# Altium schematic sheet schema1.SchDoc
size A3; ApprovedBy: CdB; CheckedBy: CdB; DrawnBy: RT; Engineer: CdB; Organization: Faber Electronics B.V.; Address1: Th. Dobbeweg 1,; Address2: 6883 GN Velp,; Address3: Netherlands; Address4: T: 026-38 46 800; DocumentNumber: 1; Revision: 2.1.4; SheetNumber: 1; SheetTotal: 6; Status: Final; PageSetup: Record=PageOptions|CenterHorizontal=True|CenterVertical=True|PrintScale=1.01|XCorrection=1.00|YCorrection=1.00|PrintKind=1|BorderSize=5000000|LeftOffset=0|BottomOffset=0|Orientation=2|PaperLength=1000|PaperWidth=1000|Scale=100|PaperSource=7|PrintQuality=1200|MediaType=1|DitherType=10|PaperKind=A3 (297 x 420mm)|PrintScaleMode=1
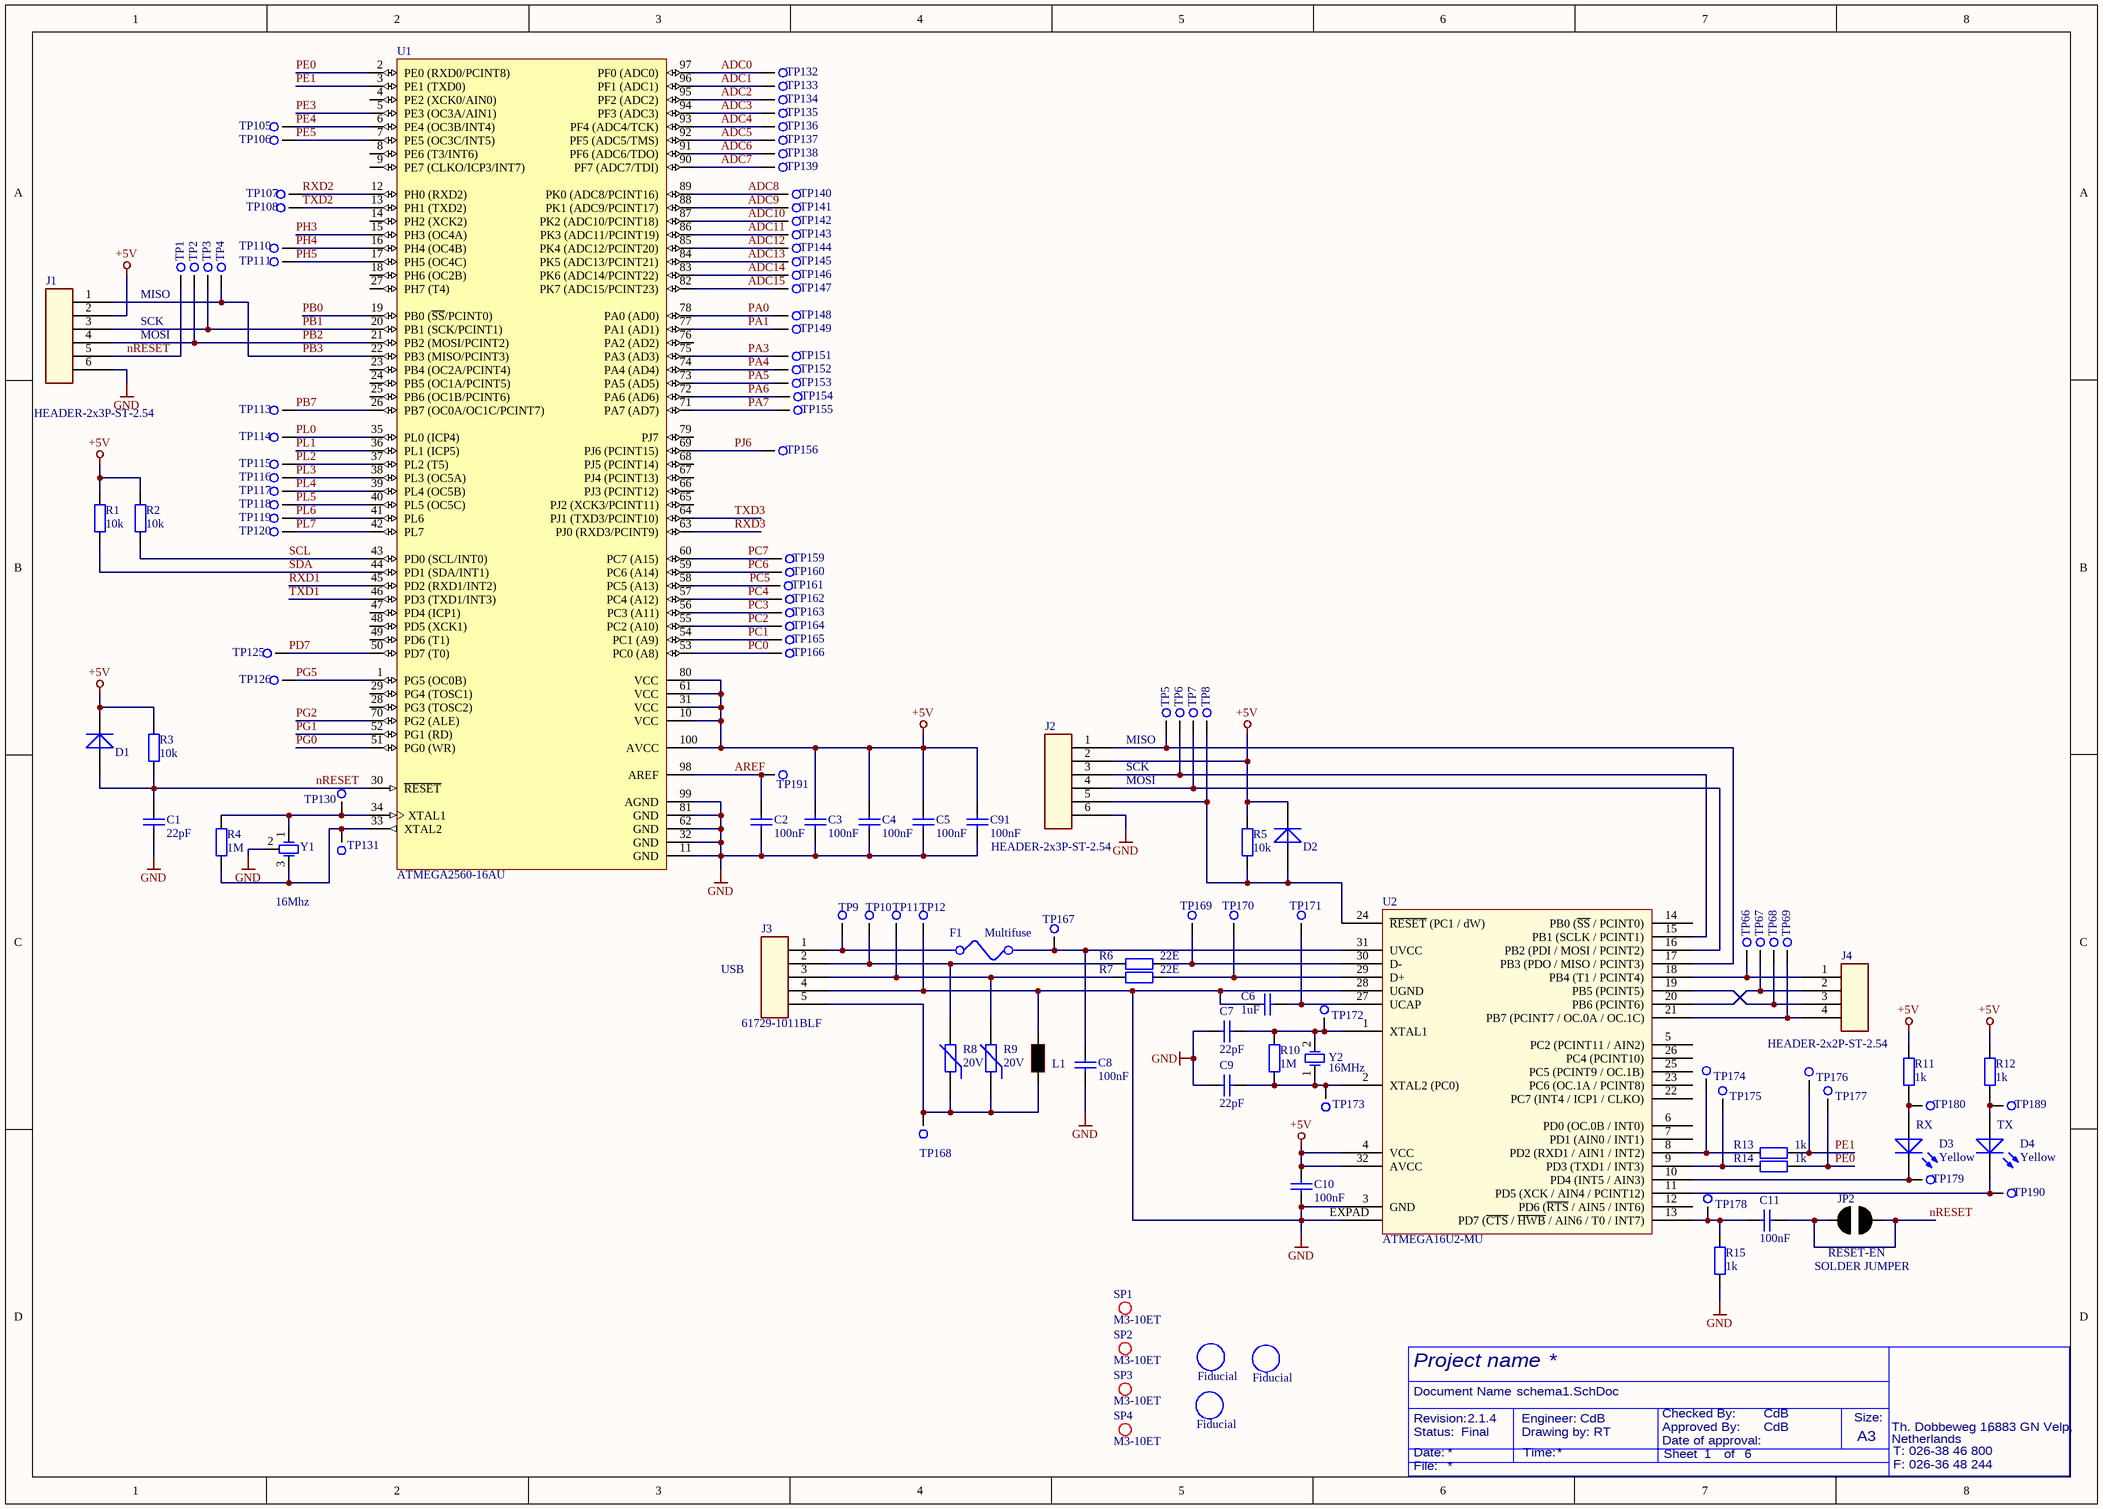
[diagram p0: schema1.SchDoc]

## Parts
C1  22pF  [C0603]
C2  100nF  [C0603]
C3  100nF  [C0603]
C4  100nF  [C0603]
C5  100nF  [C0603]
C6  1uF  [C0603]
C7  22pF  [C0603]
C8  100nF  [C0603]
C9  22pF  [C0603]
C10  100nF  [C0603]
C11  100nF  [C0603]
C91  100nF  [C0603]
D1  1N4148  [SOD323]  (value not drawn)
D2  1N4148  [SOD323]  (value not drawn)
D3  Yellow  [LED0805-YELLOW]
D4  Yellow  [LED0805-YELLOW]
F1  Multifuse  [Multifuse1812]
Fid1  Fiducial  [Fiducial]  (no BOM)
Fid2  Fiducial  [Fiducial]  (no BOM)
Fid3  Fiducial  [Fiducial]  (no BOM)
J1  HEADER-2x3P-ST-2.54  [HEADER-2x3P-ST-2.54]
J2  HEADER-2x3P-ST-2.54  [HEADER-2x3P-ST-2.54]
J3  61729-1011BLF  [61729-1011BLF]
J4  HEADER-2x2P-ST-2.54  [HEADER-2x2P-ST-2.54]
JP2  SOLDER JUMPER  [JUMPER 2 SOLDER]
L1  Bead  [L0805]  (value not drawn)
R1  10k  [R0603]
R2  10k  [R0603]
R3  10k  [R0603]
R4  1M  [R0603]
R5  10k  [R0603]
R6  22E  [R0603]
R7  22E  [R0603]
R8  20V  [R0603]
R9  20V  [R0603]
R10  1M  [R0603]
R11  1k  [R0603]
R12  1k  [R0603]
R13  1k  [R0603]
R14  1k  [R0603]
R15  1k  [R0603]
SP1  M3-10ET  [Spacer M3-10ET]
SP2  M3-10ET  [Spacer M3-10ET]
SP3  M3-10ET  [Spacer M3-10ET]
SP4  M3-10ET  [Spacer M3-10ET]
TP1  Testpoint  [Testpoint]  (value not drawn)
TP2  Testpoint  [Testpoint]  (value not drawn)
TP3  Testpoint  [Testpoint]  (value not drawn)
TP4  Testpoint  [Testpoint]  (value not drawn)
TP5  Testpoint  [Testpoint]  (value not drawn)
TP6  Testpoint  [Testpoint]  (value not drawn)
TP7  Testpoint  [Testpoint]  (value not drawn)
TP8  Testpoint  [Testpoint]  (value not drawn)
TP9  Testpoint  [Testpoint]  (value not drawn)
TP10  Testpoint  [Testpoint]  (value not drawn)
TP11  Testpoint  [Testpoint]  (value not drawn)
TP12  Testpoint  [Testpoint]  (value not drawn)
TP66  Testpoint  [Testpoint]  (value not drawn)
TP67  Testpoint  [Testpoint]  (value not drawn)
TP68  Testpoint  [Testpoint]  (value not drawn)
TP69  Testpoint  [Testpoint]  (value not drawn)
TP105  Testpoint 1.6mm  [Testpoint 1.6mm]  (value not drawn)
TP106  Testpoint 1.6mm  [Testpoint 1.6mm]  (value not drawn)
TP107  Testpoint 1.6mm  [Testpoint 1.6mm]  (value not drawn)
TP108  Testpoint 1.6mm  [Testpoint 1.6mm]  (value not drawn)
TP110  Testpoint 1.6mm  [Testpoint 1.6mm]  (value not drawn)
TP111  Testpoint 1.6mm  [Testpoint 1.6mm]  (value not drawn)
TP113  Testpoint 1.6mm  [Testpoint 1.6mm]  (value not drawn)
TP114  Testpoint 1.6mm  [Testpoint 1.6mm]  (value not drawn)
TP115  Testpoint 1.6mm  [Testpoint 1.6mm]  (value not drawn)
TP116  Testpoint 1.6mm  [Testpoint 1.6mm]  (value not drawn)
TP117  Testpoint 1.6mm  [Testpoint 1.6mm]  (value not drawn)
TP118  Testpoint 1.6mm  [Testpoint 1.6mm]  (value not drawn)
TP119  Testpoint 1.6mm  [Testpoint 1.6mm]  (value not drawn)
TP120  Testpoint 1.6mm  [Testpoint 1.6mm]  (value not drawn)
TP125  Testpoint 1.6mm  [Testpoint 1.6mm]  (value not drawn)
TP126  Testpoint 1.6mm  [Testpoint 1.6mm]  (value not drawn)
TP130  Testpoint 1.6mm  [Testpoint 1.6mm]  (value not drawn)
TP131  Testpoint 1.6mm  [Testpoint 1.6mm]  (value not drawn)
TP132  Testpoint 1.6mm  [Testpoint 1.6mm]  (value not drawn)
TP133  Testpoint 1.6mm  [Testpoint 1.6mm]  (value not drawn)
TP134  Testpoint 1.6mm  [Testpoint 1.6mm]  (value not drawn)
TP135  Testpoint 1.6mm  [Testpoint 1.6mm]  (value not drawn)
TP136  Testpoint 1.6mm  [Testpoint 1.6mm]  (value not drawn)
TP137  Testpoint 1.6mm  [Testpoint 1.6mm]  (value not drawn)
TP138  Testpoint 1.6mm  [Testpoint 1.6mm]  (value not drawn)
TP139  Testpoint 1.6mm  [Testpoint 1.6mm]  (value not drawn)
TP140  Testpoint 1.6mm  [Testpoint 1.6mm]  (value not drawn)
TP141  Testpoint 1.6mm  [Testpoint 1.6mm]  (value not drawn)
TP142  Testpoint 1.6mm  [Testpoint 1.6mm]  (value not drawn)
TP143  Testpoint 1.6mm  [Testpoint 1.6mm]  (value not drawn)
TP144  Testpoint 1.6mm  [Testpoint 1.6mm]  (value not drawn)
TP145  Testpoint 1.6mm  [Testpoint 1.6mm]  (value not drawn)
TP146  Testpoint 1.6mm  [Testpoint 1.6mm]  (value not drawn)
TP147  Testpoint 1.6mm  [Testpoint 1.6mm]  (value not drawn)
TP148  Testpoint 1.6mm  [Testpoint 1.6mm]  (value not drawn)
TP149  Testpoint 1.6mm  [Testpoint 1.6mm]  (value not drawn)
TP151  Testpoint 1.6mm  [Testpoint 1.6mm]  (value not drawn)
TP152  Testpoint 1.6mm  [Testpoint 1.6mm]  (value not drawn)
TP153  Testpoint 1.6mm  [Testpoint 1.6mm]  (value not drawn)
TP154  Testpoint 1.6mm  [Testpoint 1.6mm]  (value not drawn)
TP155  Testpoint 1.6mm  [Testpoint 1.6mm]  (value not drawn)
TP156  Testpoint 1.6mm  [Testpoint 1.6mm]  (value not drawn)
TP159  Testpoint 1.6mm  [Testpoint 1.6mm]  (value not drawn)
TP160  Testpoint 1.6mm  [Testpoint 1.6mm]  (value not drawn)
TP161  Testpoint 1.6mm  [Testpoint 1.6mm]  (value not drawn)
TP162  Testpoint 1.6mm  [Testpoint 1.6mm]  (value not drawn)
TP163  Testpoint 1.6mm  [Testpoint 1.6mm]  (value not drawn)
TP164  Testpoint 1.6mm  [Testpoint 1.6mm]  (value not drawn)
TP165  Testpoint 1.6mm  [Testpoint 1.6mm]  (value not drawn)
TP166  Testpoint 1.6mm  [Testpoint 1.6mm]  (value not drawn)
TP167  Testpoint 1.6mm  [Testpoint 1.6mm]  (value not drawn)
TP168  Testpoint 1.6mm  [Testpoint 1.6mm]  (value not drawn)
TP169  Testpoint 1.6mm  [Testpoint 1.6mm]  (value not drawn)
TP170  Testpoint 1.6mm  [Testpoint 1.6mm]  (value not drawn)
TP171  Testpoint 1.6mm  [Testpoint 1.6mm]  (value not drawn)
TP172  Testpoint 1.6mm  [Testpoint 1.6mm]  (value not drawn)
TP173  Testpoint 1.6mm  [Testpoint 1.6mm]  (value not drawn)
TP174  Testpoint 1.6mm  [Testpoint 1.6mm]  (value not drawn)
TP175  Testpoint 1.6mm  [Testpoint 1.6mm]  (value not drawn)
TP176  Testpoint 1.6mm  [Testpoint 1.6mm]  (value not drawn)
TP177  Testpoint 1.6mm  [Testpoint 1.6mm]  (value not drawn)
TP178  Testpoint 1.6mm  [Testpoint 1.6mm]  (value not drawn)
TP179  Testpoint 1.6mm  [Testpoint 1.6mm]  (value not drawn)
TP180  Testpoint 1.6mm  [Testpoint 1.6mm]  (value not drawn)
TP189  Testpoint 1.6mm  [Testpoint 1.6mm]  (value not drawn)
TP190  Testpoint 1.6mm  [Testpoint 1.6mm]  (value not drawn)
TP191  Testpoint 1.6mm  [Testpoint 1.6mm]  (value not drawn)
U1  ATMEGA2560-16AU  [TSQFP50P1600X1600X120-100N]
U2  ATMEGA16U2-MU  [QFN50P500X500X100-32-EX]
Y1  16Mhz  [CSTC]
Y2  16MHz  [XT49M-2016M]

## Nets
+5V: C3.2 C4.2 C5.2 C10.2 C91.2 D1.2(K) D2.2(K) J1.2 J2.2 R1.1 R2.1 R3.2 R5.1 R11.2 R12.2 U1.10(VCC) U1.31(VCC) U1.61(VCC) U1.80(VCC) U1.100(AVCC) U2.4(VCC) U2.32(AVCC)
GND: C1.1 C2.1 C3.1 C4.1 C5.1 C6.1 C7.1 C8.1 C9.1 C10.1 C91.1 J1.6 J2.6 J3.4 L1.1 R15.2 TP12.1 U1.11(GND) U1.32(GND) U1.62(GND) U1.81(GND) U1.99(AGND) U2.3(GND) U2.28(UGND) U2.EXPAD Y1.2
ADC0: TP132.1 U1.97(PF0_(ADC0))
ADC1: TP133.1 U1.96(PF1_(ADC1))
ADC2: TP134.1 U1.95(PF2_(ADC2))
ADC3: TP135.1 U1.94(PF3_(ADC3))
ADC4: TP136.1 U1.93(PF4_(ADC4/TCK))
ADC5: TP137.1 U1.92(PF5_(ADC5/TMS))
ADC6: TP138.1 U1.91(PF6_(ADC6/TDO))
ADC7: TP139.1 U1.90(PF7_(ADC7/TDI))
ADC8: TP140.1 U1.89(PK0_(ADC8/PCINT16))
ADC9: TP141.1 U1.88(PK1_(ADC9/PCINT17))
ADC10: TP142.1 U1.87(PK2_(ADC10/PCINT18))
ADC11: TP143.1 U1.86(PK3_(ADC11/PCINT19))
ADC12: TP144.1 U1.85(PK4_(ADC12/PCINT20))
ADC13: TP145.1 U1.84(PK5_(ADC13/PCINT21))
ADC14: TP146.1 U1.83(PK6_(ADC14/PCINT22))
ADC15: TP147.1 U1.82(PK7_(ADC15/PCINT23))
AREF: C2.2 TP191.1 U1.98(AREF)
nRESET: C1.2 C11.1 D1.1(A) J1.5 JP2.1 JP2.2 R3.1 TP1.1 U1.30(~{RESET})
PA0: TP148.1 U1.78(PA0_(AD0))
PA1: TP149.1 U1.77(PA1_(AD1))
PA3: TP151.1 U1.75(PA3_(AD3))
PA4: TP152.1 U1.74(PA4_(AD4))
PA5: TP153.1 U1.73(PA5_(AD5))
PA6: TP154.1 U1.72(PA6_(AD6))
PA7: TP155.1 U1.71(PA7_(AD7))
PB0: U1.19(PB0_(~{SS}/PCINT0))
PB1: J1.3 TP3.1 U1.20(PB1_(SCK/PCINT1))
PB2: J1.4 TP2.1 U1.21(PB2_(MOSI/PCINT2))
PB3: J1.1 TP4.1 U1.22(PB3_(MISO/PCINT3))
PB7: TP113.1 U1.26(PB7_(OC0A/OC1C/PCINT7))
PC0: TP166.1 U1.53(PC0_(A8))
PC1: TP165.1 U1.54(PC1_(A9))
PC2: TP164.1 U1.55(PC2_(A10))
PC3: TP163.1 U1.56(PC3_(A11))
PC4: TP162.1 U1.57(PC4_(A12))
PC5: TP161.1 U1.58(PC5_(A13))
PC6: TP160.1 U1.59(PC6_(A14))
PC7: TP159.1 U1.60(PC7_(A15))
PD7: TP125.1 U1.50(PD7_(T0))
PE0: R14.2 TP177.1 U1.2(PE0_(RXD0/PCINT8))
PE1: R13.2 TP176.1 U1.3(PE1_(TXD0))
PE3: U1.5(PE3_(OC3A/AIN1))
PE4: TP105.1 U1.6(PE4_(OC3B/INT4))
PE5: TP106.1 U1.7(PE5_(OC3C/INT5))
PG0: U1.51(PG0_(WR))
PG1: U1.52(PG1_(RD))
PG2: U1.70(PG2_(ALE))
PG5: TP126.1 U1.1(PG5_(OC0B))
PH3: U1.15(PH3_(OC4A))
PH4: TP110.1 U1.16(PH4_(OC4B))
PH5: TP111.1 U1.17(PH5_(OC4C))
PJ6: TP156.1 U1.69(PJ6_(PCINT15))
PL0: TP114.1 U1.35(PL0_(ICP4))
PL1: U1.36(PL1_(ICP5))
PL2: TP115.1 U1.37(PL2_(T5))
PL3: TP116.1 U1.38(PL3_(OC5A))
PL4: TP117.1 U1.39(PL4_(OC5B))
PL5: TP118.1 U1.40(PL5_(OC5C))
PL6: TP119.1 U1.41(PL6)
PL7: TP120.1 U1.42(PL7)
RXD1: U1.45(PD2_(RXD1/INT2))
RXD2: TP107.1 U1.12(PH0_(RXD2))
RXD3: U1.63(PJ0_(RXD3/PCINT9))
SCL: R2.2 U1.43(PD0_(SCL/INT0))
SDA: R1.2 U1.44(PD1_(SDA/INT1))
TXD1: U1.46(PD3_(TXD1/INT3))
TXD2: TP108.1 U1.13(PH1_(TXD2))
TXD3: U1.64(PJ1_(TXD3/PCINT10))
NetC6_2: C6.2 TP171.1 U2.27(UCAP)
NetC7_2: C7.2 R10.2 TP172.1 U2.1(XTAL1) Y2.2
NetC8_2: C8.2 F1.2 TP167.1 U2.31(UVCC)
NetC9_2: C9.2 R10.1 TP173.1 U2.2(XTAL2_(PC0)) Y2.1
NetC11_2: C11.2 R15.1 TP178.1 U2.13(PD7_(~{CTS}_/_~{HWB}_/_AIN6_/_T0_/_INT7))
NetD2_1: D2.1(A) J2.5 R5.2 TP8.1 U2.24(~{RESET}_(PC1_/_dW))
NetD3_1: D3.1(A) R11.1 TP180.1
NetD3_2: D3.2(K) TP179.1 U2.10(PD4_(INT5_/_AIN3))
NetD4_1: D4.1(A) R12.1 TP189.1
NetD4_2: D4.2(K) TP190.1 U2.11(PD5_(XCK_/_AIN4_/_PCINT12))
NetF1_1: F1.1 J3.1 TP9.1
NetJ2_1: J2.1 TP5.1 U2.17(PB3_(PDO_/_MISO_/_PCINT3))
NetJ2_3: J2.3 TP6.1 U2.15(PB1_(SCLK_/_PCINT1))
NetJ2_4: J2.4 TP7.1 U2.16(PB2_(PDI_/_MOSI_/_PCINT2))
NetJ3_2: J3.2 R6.1 R8.2 TP10.1
NetJ3_3: J3.3 R7.1 R9.2 TP11.1
NetJ3_5: J3.5 L1.2 R8.1 R9.1 TP168.1
NetJ4_1: J4.1 TP66.1 U2.18(PB4_(T1_/_PCINT4))
NetJ4_2: J4.2 TP67.1 U2.20(PB6_(PCINT6))
NetJ4_3: J4.3 TP68.1 U2.19(PB5_(PCINT5))
NetJ4_4: J4.4 TP69.1 U2.21(PB7_(PCINT7_/_OC.0A_/_OC.1C))
NetR4_1: R4.1 TP131.1 U1.33(XTAL2) Y1.3
NetR4_2: R4.2 TP130.1 U1.34(XTAL1) Y1.1
NetR6_2: R6.2 TP169.1 U2.30(D-)
NetR7_2: R7.2 TP170.1 U2.29(D+)
NetR13_1: R13.1 TP174.1 U2.8(PD2_(RXD1_/_AIN1_/_INT2))
NetR14_1: R14.1 TP175.1 U2.9(PD3_(TXD1_/_INT3))

Not connected (* = marked no-connect by the designer): U1 4(PE2_(XCK0/AIN0)) 8(PE6_(T3/INT6)) 9(PE7_(CLKO/ICP3/INT7)) 14(PH2_(XCK2)) 18(PH6_(OC2B)) 23(PB4_(OC2A/PCINT4)) 24(PB5_(OC1A/PCINT5)) 25(PB6_(OC1B/PCINT6)) 27(PH7_(T4)) 28(PG3_(TOSC2)) 29(PG4_(TOSC1)) 47(PD4_(ICP1)) 48(PD5_(XCK1)) 49(PD6_(T1)) 65(PJ2_(XCK3/PCINT11)) 66(PJ3_(PCINT12)) 67(PJ4_(PCINT13)) 68(PJ5_(PCINT14)) 76(PA2_(AD2)) 79(PJ7); U2 5(PC2_(PCINT11_/_AIN2)) 6(PD0_(OC.0B_/_INT0)) 7(PD1_(AIN0_/_INT1)) 12(PD6_(~{RTS}_/_AIN5_/_INT6)) 14(PB0_(~{SS}_/_PCINT0)) 22(PC7_(INT4_/_ICP1_/_CLKO)) 23(PC6_(OC.1A_/_PCINT8)) 25(PC5_(PCINT9_/_OC.1B)) 26(PC4_(PCINT10))

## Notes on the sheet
- MISO
- SCK
- MOSI
- (near J3) USB
- RX
- TX
- (near JP2) RESET-EN

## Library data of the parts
C1 C7 C9 = Library_CAP-0008: RO C0G 22pF 2% 50V  0603; Faber ItemCode: 35321100
C2-C5 C8 C10 C11 C91 = Library_CAP-0002: RO X7R 100nF 10% 50V 0603; Faber ItemCode: 45068500
C6 = Library_CAP-0006: RO X5R 1uF 10% 10V 0603; Faber ItemCode: 36310600
D1 D2 = Library_DIO-0002: RO DIODE 1N4148WS-V-GS08 SOT-323  VISHAY; Faber ItemCode: 36650500; Info: Small Signal Fast Switching Diode
D3 D4 = Library_LED-0003: RO LED GEEL HSMY-C170 0805  AVAGO; Faber ItemCode: 35160800
F1 = Library_FUSE-0001: RO ZEK MULTI 500MA SMD 1812 MF-MSMF050-2 BOURNS; Faber ItemCode: 35502800; Info: MULTIFUSE, SMD, 0.5A; Value: 0.5A
Fid1-Fid3 = Library_MISC-0003
J1 J2 = Library_CON-0003: RO CONN PR HDR 2X3P H4B-06DS-0000 INT; Faber ItemCode: 35149900
J3 = Library_CON-0001: RO CONN PR USB-B HKS 61729-1011BLF FCI; Faber ItemCode: 36924400
J4 = Library_CON-0011: HDR 2X2P
JP2 = Library_CON-0010
L1 = Library_COIL-0001: RO FERRIET BLM21PG221SN1D  0805; Faber ItemCode: 36571200
R1-R3 R5 = Library_RES-0001: RO RES 10k0 1% 0,063W  0603; Faber ItemCode: 36084500
R4 R10 = Library_RES-0003: RO RES 1M0 1% 0,1W 0603; Faber ItemCode: 36059900
R6 R7 = Library_RES-0007: RO RES 22E0 1% 0,063W 0603; Faber ItemCode: 36108300
R8 R9 = Library_RES-0012: RO VDR 0603 CG0603MLC-05E; Mfg: BOURNS; Faber ItemCode: 36925900
R11-R15 = Library_RES-0004: RO RES 1k0 1% 0,1W  0603; Faber ItemCode: 34637900
SP1 = Spacer M3-10ET: MOER-SMD SMTSO-M3-10ET  PEM; Faber ItemCode: 36462900; Bestel grote: 300; Prijs: 0.4311
SP2-SP4 = Spacer M3-10ET: Spacer SMTSO-M3-10ET; Faber ItemCode: 36462900; Mfg: PEM; Faber Artikelomschrijving: MOER-SMD SMTSO-M3-10ET  PEM; Bestel grote: 300; Prijs: 0.4311
TP1-TP12 TP66-TP69 = Library_MISC-0001: Info: Testpoint, 2mm, round
TP105-TP108 TP110 TP111 TP113-TP120 TP125 TP126 TP130-TP149 TP151-TP156 TP159-TP180 TP189-TP191 = Testpoint 1.6mm: ID: Library_MISC-0001
U1 = Library_ICS-0001: RO IC ATMEGA2560-16AU TQFP-100 ATMEL; Info: 8-bit Atmel Microcontroller with 256KB Flash, 4KB EEPROM, 8KB RAM; Faber ItemCode: 36924700
U2 = Library_ICS-0004: RO IC ATMEGA16U2-MU QFN-32 ATMEL; Info: 8-bit Microcontroller with 16K Bytes of ISP Flash and USB Controller; Faber ItemCode: 36924600
Y1 = LIBRARY_XTAL-0002: RO KRIS 16MHz CSTCE16M0V53-R0 SMD MURATA; Info: Build in cap; Faber ItemCode: 36925600
Y2 = LIBRARY_XTAL-0001: RO KRISTAL 16.0MHz  HC49/4HSMX  SMD CMAC; Info: Low Profile SMD Type Crystal Units; Faber ItemCode: 36298900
